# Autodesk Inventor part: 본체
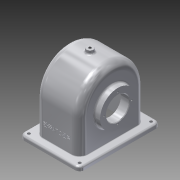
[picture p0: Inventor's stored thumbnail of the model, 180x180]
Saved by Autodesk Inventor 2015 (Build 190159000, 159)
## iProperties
Created: 2016-01
Part Number: 본체
Material: 알루미늄 6061
Document SubType Name: Modeling
Designer: Administrator
Density: 2.7 g/cm^3
Appearance: 알루미늄 - 평지
Mass: 806.765 g
Surface Area: 999.207 cm^2
Volume: 298.802 cm^3
Author: Administrator
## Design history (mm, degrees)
sketch "스케치1"
  geometry: L1 (-52, 70)-(52, 70); L2 (52, 70)-(52, -70); L3 (52, -70)-(-52, -70); L4 (-52, -70)-(-52, 70); C1 r 2.5 at (-44, 62); C2 r 2.5 at (44, 62); C3 r 2.5 at (-44, -62); C4 r 2.5 at (44, -62); 3 further points
  constraints: 8 end point, 4 centre point, 2 midpoint, 2 parallel, 1 horizontal, 1 horizontal alignment, 1 perpendicular, 1 vertical alignment
  dimensions: "d0" = 104 distance between parallel lines of L2 L4; "d1" = 140 distance between parallel lines of L3 L1; "d2" = 5 diameter of C1; "d3" = 8 distance from line of C1.centre L1; "d4" = 8 distance from line of L4 C1.centre
extrude "돌출1" new body sketch "스케치1" distance "d5" = 7; taper "d6" = 0 deg
sketch "스케치3"
  geometry: L1 (-57, 64)-(-57, 0); L2 (57, 64)-(57, 0); L3 (70, 0)-(-70, 0) reference; A1 r 57 centre (0, 64) between (57, 64) and (-57, 64); 1 further point
  constraints: 4 end point, 2 point on circle, 2 point on line, 2 vertical, 1 centre point, 1 tangent
  dimensions: "d7" = 114 diameter of A1; "d8" = 64 distance from line of L3 A1.centre
extrude "돌출2" join sketch "스케치3" stored distance "d9" = 77; taper "d10" = 0 deg
node "작업 평면1"
sketch "스케치5"
  geometry: L1 (0, 70)-(0, -70) reference; C1 r 31 at (60, 0); 1 further point
  constraints: 1 centre point
  dimensions: "d13" = 62 diameter of C1; "d82" = 60 distance from line of L1 C1.centre
extrude "돌출3" join sketch "스케치5" stored distance "d14" = 77; taper "d15" = 0 deg
sketch "스케치6"
  geometry: L1 (57, 7)-(57, 64) reference; L2 (-57, 64)-(-57, 7) reference; L3 (-51, 0)-(-51, 64); L4 (51, 64)-(51, 0); L5 (70, 0)-(-70, 0) reference; A1 r 57 centre (0, 64) between (57, 64) and (-57, 64) reference; A2 r 51 centre (0, 64) between (51, 64) and (-51, 64); 1 further point
  constraints: 4 end point, 2 point on circle, 2 point on line, 1 centre point
  dimensions: "d16" = 6 radial gap between concentric circles of A1 A2
extrude "돌출4" cut sketch "스케치6" stored distance "d17" = 67; taper "d18" = 0 deg
node "작업 평면2"
sketch "스케치8"
  geometry: L1 (0, 51)-(0, -51) reference; C1 r 28 at (-60, 0); 1 further point
  constraints: 1 centre point
  dimensions: "d85" = 60 distance from line of L1 C1.centre
extrude "돌출5" join sketch "스케치8" stored distance "d21" = 67; taper "d22" = 40 deg
sketch "스케치9"
  geometry: L1 (53, 57)-(53, -57); L2 (-4, -57)-(53, -57); L3 (60, 70)-(60, -70) reference; C1 r 20 at (0, 0); 1 further point
  constraints: 1 centre point
  dimensions: "d23" = 40 diameter of C1; "d83" = 60 distance from line of L3 C1.centre
extrude "돌출6" cut sketch "스케치9" stored distance "d24" = 67; taper "d25" = 0 deg
sketch "스케치11"
  geometry: L1 (53, -57)-(53, 57); L2 (53, -57)-(-4, -57); L3 (-4, 57)-(53, 57); L4 (60, 51)-(60, -51) reference; C1 r 20 at (0, 0); A1 r 57.14 centre (0, 0) between (-4, 57) and (-4, -57); 1 further point
  constraints: 2 centre point, 2 point on circle, 1 coincident
  dimensions: "d31" = 40 diameter of C1; "d104" = 60 distance from line of L4 A1.centre
extrude "돌출7" cut sketch "스케치11" distance "d32" = 16; taper "d33" = 0 deg
node "작업 평면3"
sketch "스케치12"
  geometry: C1 r 6 at (0, 0); 1 further point
  constraints: 1 centre point, 1 coincident
  dimensions: "d35" = 12 diameter of C1
extrude "돌출8" join sketch "스케치12" stored distance "d36" = 16; taper "d37" = 0 deg
sketch "스케치13"
  geometry: 2 further points
  constraints: 1 coincident
hole "구멍1" sketch "스케치13" at (0, 0) diameter "d38" = 4.459; stored, may be unused: countersink angle "d42" = 90 deg, drill point angle "d44" = 118 deg; dims "d39" = 10, "d40" = 4, "d41" = 2, "d43" = 12.8
sketch "스케치14" dims "d45" = 48
  geometry: L1 (60, -51)-(60, 51) reference; 4 further points
  constraints: 1 coincident, 1 horizontal alignment, 2 other
  dimensions: "d84" = 60 distance from line of L1 point (0, 0)
hole "구멍2" sketch "스케치14" at (-24, 0) diameter "d46" = 2.459; stored, may be unused: countersink angle "d50" = 90 deg, drill point angle "d52" = 118 deg; dims "d47" = 6, "d48" = 4, "d49" = 2, "d51" = 8
sketch "스케치17"
  geometry: L1 (90.5, -7)-(-13.5, -7) reference; 3 further points
  constraints: 1 midpoint, 1 vertical alignment, 1 other
  dimensions: "d70" = 30 distance from line of L1 point (38.5, 23)
feature "엠보싱1" sketch "스케치17" dims "d0" = 104, "d1" = 140, "d2" = 5, "d3" = 8, "d4" = 8, "d71" = 0.5, "d72" = 0
chamfer "모따기1" distance "d73" = 1; stored, may be unused: second distance "d74" = 2, angle "d75" = 45 deg
fillet "모깎기1" dims "d76" = 1, "d77" = 9, "d78" = 14, "d79" = 8, "d80" = 3
sketch "스케치20"
  geometry: L1 (38.5, 97.416)-(38.5, 64); L2 (35.5, 64)-(35.5, 84); L3 (35.5, 64)-(38.5, 64); L4 (35.5, 94.899)-(38.5, 97.416); L5 (35.5, 94.899)-(35.5, 64); 1 further point
  constraints: 10 end point, 1 horizontal
revolve "회전2" sketch "스케치20" stored, may be unused: angle "d88" = 90 deg
sketch "스케치21" dims "d89" = 56
  geometry: C1 r 30.899 at (0, 0) reference; 3 further points
  constraints: 1 coincident, 1 horizontal alignment, 2 other
hole "구멍4" sketch "스케치21" at (28, 0) diameter "d90" = 2.459; stored, may be unused: countersink angle "d94" = 90 deg, drill point angle "d96" = 118 deg; dims "d91" = 7, "d92" = 4, "d93" = 2, "d95" = 9
fillet "모깎기2" dims "d100" = 3
chamfer "모따기2" distance "d101" = 1; stored, may be unused: second distance "d102" = 2, angle "d103" = 45 deg
node "솔리드1"
pattern_circular "원형 패턴1" dims angle "d54" = 360 deg
pattern_circular "원형 패턴3" dims angle "d98" = 360 deg
other parameters: "d12" = -87, "d19" = 14, "d34" = -127
